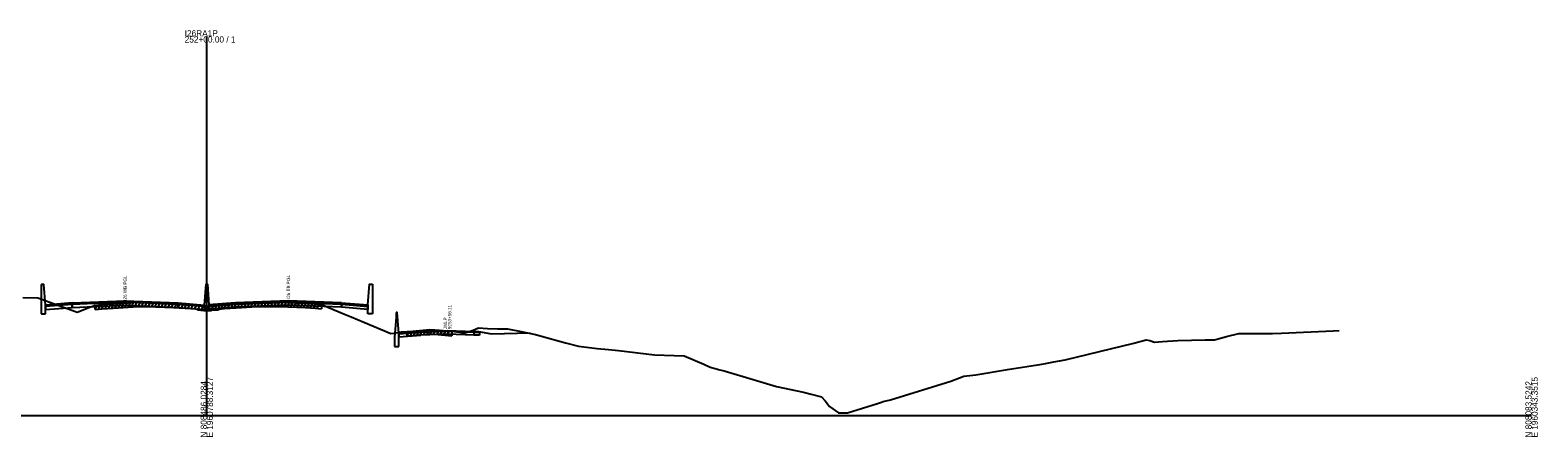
# Model space of a CAD drawing. Extents: x 1017 to 19997, y -1947 to 50737.
# Drawn here: x 10520 to 11203, y 1990 to 2175 of the extents above; entities that cross this region are included whole.
import ezdxf

# ---------------------------------------------------------------- set-up
doc = ezdxf.new("R2010")
doc.units = 0
for name, color, linetype in [('RD_GPK_XS_Cell', 7, 'Continuous'), ('RD_XS_Base', 7, 'Continuous'), ('RD_XS_ExGround', 7, 'Continuous'), ('RD_XS_ExPaveRet', 7, 'Continuous'), ('RD_XS_Greenside', 7, 'Continuous'), ('RD_XS_MedBWall', 7, 'Continuous'), ('RD_XS_Pave', 7, 'Continuous'), ('RD_XS_PaveOvlay', 7, 'Continuous'), ('RD_XS_TX_Notes', 7, 'Continuous')]:
    doc.layers.add(name, color=color, linetype=linetype)

msp = doc.modelspace()

# ---------------------------------------------------------------- linework, layer by layer
at = {"layer": 'RD_GPK_XS_Cell'}
for p, q in [((10600, 2000), (10600, 2171.99)), ((10000, 2000), (10600, 2000)), ((10600, 2000), (11200, 2000))]:
    msp.add_line(p, q, dxfattribs=at)
at = {"layer": 'RD_XS_Base'}
for points in [[(10539, 2050.38), (10527, 2049.42)], [(10527, 2049.42), (10527, 2048.08)], [(10527, 2048.08), (10539, 2049.04)], [(10539, 2049.04), (10539, 2050.38)], [(10539.05, 2049.05), (10539, 2049.04)], [(10539.05, 2050.39), (10539.05, 2049.05)], [(10539.05, 2049.05), (10563, 2050.02), (10587, 2049.05)], [(10587, 2049.05), (10587, 2050.39)], [(10599, 2049.45), (10587, 2050.39)], [(10587, 2049.05), (10599, 2048.11)], [(10599, 2048.11), (10599, 2049.45)], [(10601, 2048.18), (10601, 2049.52)], [(10613, 2049.12), (10601, 2048.18)], [(10613, 2049.12), (10613, 2050.46)], [(10660.95, 2049.13), (10637, 2050.09), (10613, 2049.12)], [(10660.95, 2049.13), (10660.95, 2050.47)], [(10661, 2049.12), (10660.95, 2049.13)], [(10661, 2050.46), (10661, 2049.12)], [(10661, 2050.46), (10673, 2049.5)], [(10661, 2049.12), (10661, 2050.46)], [(10673, 2048.16), (10661, 2049.12)], [(10673, 2049.5), (10673, 2048.16)], [(10697, 2037.82), (10687, 2037.02)], [(10687, 2037.02), (10687, 2035.69)], [(10687, 2035.69), (10697, 2036.49)], [(10697, 2037.82), (10709, 2038.3), (10721, 2037.82)], [(10697, 2036.49), (10697, 2037.82)], [(10721, 2036.51), (10709, 2036.97), (10697, 2036.49)], [(10721, 2037.82), (10721, 2036.51)], [(10721, 2037.82), (10723, 2037.74), (10723.5, 2037.72)], [(10723.5, 2036.39), (10721, 2036.51)], [(10723.5, 2037.72), (10723.5, 2036.39)]]:
    msp.add_lwpolyline(points, dxfattribs=at)
at = {"layer": 'RD_XS_ExGround'}
msp.add_lwpolyline([(10516.61, 2053.55), (10523.41, 2053.42), (10540.55, 2047.19), (10541.28, 2046.94), (10541.68, 2047.07), (10545.82, 2048.63), (10547.45, 2049.26), (10549.47, 2050.1), (10552.47, 2050.33), (10557.64, 2050.72), (10564.45, 2051.19), (10569.1, 2051.49), (10572.85, 2051.39), (10580.96, 2051.12), (10584.86, 2050.93), (10592.74, 2050.55), (10594.7, 2050.36), (10595.61, 2050.26), (10595.76, 2049.93), (10598.72, 2049.61), (10599.07, 2049.58), (10600, 2049.62), (10601.83, 2049.7), (10602.13, 2049.72), (10604.94, 2049.92), (10605.64, 2050.13), (10605.83, 2050.3), (10606.6, 2050.38), (10607.99, 2050.54), (10613.27, 2050.85), (10620.36, 2051.3), (10631.64, 2051.46), (10632.24, 2051.47), (10632.79, 2051.45), (10644.63, 2050.96), (10649.24, 2050.63), (10652, 2050.41), (10662.41, 2046.01), (10665.43, 2044.73), (10671.15, 2042.35), (10683.42, 2037.19), (10684.87, 2037.38), (10688.25, 2037.99), (10690.77, 2038.18), (10693.31, 2038.34), (10700.95, 2039.03), (10703.23, 2038.91), (10711.02, 2038.21), (10715.49, 2037.62), (10716.62, 2037.38), (10720.58, 2038.72), (10723.11, 2039.72), (10727.11, 2039.47), (10731.64, 2039.34), (10736.21, 2039.25), (10742.45, 2038.15), (10748.9, 2036.82), (10762.39, 2033.01), (10768.42, 2031.5), (10776.86, 2030.43), (10781.9, 2029.95), (10786.5, 2029.45), (10802.77, 2027.57), (10811.69, 2027.18), (10816.13, 2027.09), (10825.04, 2023.3), (10828.05, 2021.99), (10830.21, 2021.38), (10832.29, 2020.79), (10834.27, 2020.33), (10847.49, 2016.27), (10857.95, 2013.11), (10870.25, 2010.57), (10873.72, 2009.67), (10878.46, 2008.45), (10880.02, 2006.69), (10882, 2004.14), (10886.12, 2001.16), (10888.78, 2001.19), (10890.21, 2001.22), (10903.84, 2005.47), (10905.64, 2006.08), (10906.37, 2006.35), (10909.59, 2007.13), (10936.93, 2015.61), (10942.91, 2017.89), (10948.32, 2018.45), (10962.68, 2020.95), (10978.23, 2023.27), (10979.88, 2023.65), (10983.68, 2024.34), (10988.77, 2025.2), (11019.89, 2032.79), (11025.45, 2034.28), (11027.12, 2034), (11029.16, 2033.34), (11032.88, 2033.63), (11039.73, 2034), (11052.15, 2034.29), (11055.34, 2034.39), (11056.35, 2034.39), (11061.8, 2035.82), (11067.43, 2037.25), (11069.41, 2037.26), (11082.64, 2037.14), (11086.72, 2037.33), (11110.14, 2038.38), (11112.83, 2038.58)], dxfattribs=at)
at = {"layer": 'RD_XS_ExPaveRet'}
for p, q in [((10549.47, 2048.1), (10550.51, 2050.18)), ((10549.47, 2048.1), (10549.47, 2050.1)), ((10550.97, 2048.21), (10552.01, 2050.29)), ((10552.47, 2048.33), (10553.51, 2050.41)), ((10552.47, 2048.33), (10557.64, 2048.72)), ((10553.97, 2048.44), (10555.01, 2050.52)), ((10555.47, 2048.56), (10556.51, 2050.64)), ((10556.97, 2048.67), (10558.01, 2050.75)), ((10557.64, 2048.72), (10564.45, 2049.19)), ((10558.47, 2048.78), (10559.5, 2050.85)), ((10559.97, 2048.88), (10561, 2050.95)), ((10561.47, 2048.98), (10562.5, 2051.06)), ((10562.97, 2049.09), (10564, 2051.16)), ((10564.45, 2049.19), (10569.1, 2049.49)), ((10564.47, 2049.19), (10565.5, 2051.26)), ((10565.97, 2049.29), (10567, 2051.35)), ((10567.47, 2049.39), (10568.5, 2051.45)), ((10568.97, 2049.48), (10569.96, 2051.47)), ((10569.1, 2049.49), (10572.85, 2049.39)), ((10570.47, 2049.45), (10571.45, 2051.43)), ((10571.97, 2049.41), (10572.95, 2051.38)), ((10572.85, 2049.39), (10580.96, 2049.12)), ((10573.47, 2049.37), (10574.45, 2051.33)), ((10574.97, 2049.32), (10575.95, 2051.28)), ((10576.47, 2049.27), (10577.45, 2051.23)), ((10577.97, 2049.22), (10578.95, 2051.18)), ((10579.47, 2049.17), (10580.45, 2051.13)), ((10580.96, 2049.12), (10584.86, 2048.93)), ((10580.97, 2049.12), (10581.94, 2051.07)), ((10582.47, 2049.05), (10583.44, 2051)), ((10583.97, 2048.97), (10584.94, 2050.93)), ((10584.86, 2048.93), (10592.74, 2048.55)), ((10585.47, 2048.9), (10586.44, 2050.85)), ((10586.97, 2048.83), (10587.94, 2050.78)), ((10588.47, 2048.76), (10589.44, 2050.71)), ((10589.97, 2048.69), (10590.94, 2050.64)), ((10591.47, 2048.61), (10592.44, 2050.57)), ((10592.74, 2048.55), (10594.7, 2048.36)), ((10592.97, 2048.53), (10593.92, 2050.44)), ((10594.47, 2048.38), (10595.42, 2050.28)), ((10595.97, 2047.9), (10596.92, 2049.8)), ((10597.47, 2047.74), (10598.42, 2049.64)), ((10598.97, 2047.59), (10599.98, 2049.62)), ((10600.47, 2047.64), (10601.49, 2049.68)), ((10601.97, 2047.71), (10603, 2049.78)), ((10603.47, 2047.81), (10604.5, 2049.89)), ((10604.97, 2047.92), (10606.17, 2050.33)), ((10606.47, 2048.37), (10607.53, 2050.48)), ((10606.6, 2048.38), (10607.99, 2048.54)), ((10607.97, 2048.53), (10609, 2050.6)), ((10607.99, 2048.54), (10613.27, 2048.85)), ((10609.47, 2048.63), (10610.5, 2050.69)), ((10610.97, 2048.72), (10612, 2050.78)), ((10612.47, 2048.81), (10613.5, 2050.87)), ((10613.27, 2048.85), (10620.36, 2049.3)), ((10613.97, 2048.9), (10615, 2050.96)), ((10615.47, 2048.99), (10616.5, 2051.06)), ((10616.97, 2049.09), (10618, 2051.15)), ((10618.47, 2049.18), (10619.5, 2051.25)), ((10619.97, 2049.28), (10620.98, 2051.31)), ((10620.36, 2049.3), (10631.64, 2049.46)), ((10621.47, 2049.32), (10622.47, 2051.33)), ((10622.97, 2049.34), (10623.97, 2051.35)), ((10624.47, 2049.36), (10625.47, 2051.37)), ((10625.97, 2049.38), (10626.97, 2051.4)), ((10627.47, 2049.4), (10628.47, 2051.42)), ((10628.97, 2049.42), (10629.97, 2051.44)), ((10630.47, 2049.45), (10631.47, 2051.46)), ((10631.64, 2049.46), (10632.24, 2049.47)), ((10631.97, 2049.47), (10632.95, 2051.44)), ((10632.24, 2049.47), (10632.79, 2049.45)), ((10632.79, 2049.45), (10644.63, 2048.96)), ((10633.47, 2049.42), (10634.45, 2051.38)), ((10634.97, 2049.36), (10635.95, 2051.32)), ((10636.47, 2049.3), (10637.45, 2051.26)), ((10637.97, 2049.24), (10638.95, 2051.2)), ((10639.47, 2049.17), (10640.45, 2051.13)), ((10640.97, 2049.11), (10641.95, 2051.07)), ((10642.47, 2049.05), (10643.45, 2051.01)), ((10643.97, 2048.99), (10644.94, 2050.94)), ((10644.63, 2048.96), (10649.24, 2048.63)), ((10645.47, 2048.9), (10646.43, 2050.83)), ((10646.97, 2048.79), (10647.93, 2050.72)), ((10648.47, 2048.69), (10649.43, 2050.61)), ((10649.24, 2048.63), (10652, 2048.41)), ((10649.97, 2048.57), (10650.93, 2050.5)), ((10652, 2050.41), (10652, 2048.41)), ((10549.47, 2048.1), (10552.47, 2048.33)), ((10594.7, 2048.36), (10595.61, 2048.26)), ((10595.61, 2048.26), (10595.76, 2047.93)), ((10595.76, 2047.93), (10598.72, 2047.61)), ((10598.72, 2047.61), (10599.07, 2047.58)), ((10599.07, 2047.58), (10600, 2047.62)), ((10600, 2047.62), (10601.83, 2047.7)), ((10601.83, 2047.7), (10602.13, 2047.72)), ((10602.13, 2047.72), (10604.94, 2047.92)), ((10604.94, 2047.92), (10605.64, 2048.13)), ((10605.64, 2048.13), (10605.83, 2048.3)), ((10605.83, 2048.3), (10606.6, 2048.38)), ((10690.77, 2036.18), (10691.81, 2038.24)), ((10690.77, 2036.18), (10690.77, 2038.18)), ((10690.77, 2036.18), (10693.31, 2036.34)), ((10692.27, 2036.27), (10693.31, 2038.34)), ((10693.31, 2036.34), (10700.95, 2037.03)), ((10693.77, 2036.38), (10694.82, 2038.47)), ((10695.27, 2036.51), (10696.32, 2038.61)), ((10696.77, 2036.65), (10697.82, 2038.74)), ((10698.27, 2036.79), (10699.32, 2038.88)), ((10699.77, 2036.92), (10700.82, 2039.02)), ((10700.95, 2037.03), (10703.23, 2036.91)), ((10701.27, 2037.01), (10702.25, 2038.96)), ((10702.77, 2036.93), (10703.74, 2038.86)), ((10703.23, 2036.91), (10711.02, 2036.21)), ((10704.27, 2036.81), (10705.23, 2038.73)), ((10705.77, 2036.68), (10706.73, 2038.59)), ((10707.27, 2036.55), (10708.23, 2038.46)), ((10708.77, 2036.41), (10709.73, 2038.33)), ((10711.02, 2038.21), (10711.02, 2036.21))]:
    msp.add_line(p, q, dxfattribs=at)
at = {"layer": 'RD_XS_Greenside'}
for points in [[(10723, 2038.06), (10729, 2037.1)], [(10729, 2037.1), (10746.46, 2037.48)]]:
    msp.add_lwpolyline(points, dxfattribs=at)
at = {"layer": 'RD_XS_MedBWall'}
for points in [[(10527, 2050.1), (10526.25, 2059.44), (10525, 2059.44)], [(10525, 2059.44), (10525, 2046.1)], [(10599, 2050.11), (10599.75, 2059.52), (10600.25, 2059.52), (10601, 2050.18)], [(10673, 2050.18), (10673.75, 2059.52), (10675, 2059.52)], [(10675, 2059.52), (10675, 2046.18)], [(10527, 2046.1), (10527, 2050.1)], [(10599, 2048.11), (10599, 2050.11)], [(10601, 2050.18), (10601, 2048.11)], [(10673, 2046.18), (10673, 2050.18)], [(10525, 2046.1), (10527, 2046.1)], [(10601, 2048.11), (10599, 2048.11)], [(10675, 2046.18), (10673, 2046.18)], [(10685.75, 2044.68), (10685, 2035.34)], [(10687, 2037.34), (10686.25, 2046.68), (10685.75, 2046.68)], [(10685.75, 2046.68), (10685.75, 2044.68)], [(10685, 2035.34), (10685, 2031.34)], [(10687, 2031.34), (10687, 2037.34)], [(10685, 2031.34), (10687, 2031.34)]]:
    msp.add_lwpolyline(points, dxfattribs=at)
at = {"layer": 'RD_XS_Pave'}
for points in [[(10539, 2050.72), (10527, 2049.76)], [(10527, 2049.76), (10527, 2049.42)], [(10539, 2050.38), (10539, 2050.72)], [(10539.05, 2050.39), (10539, 2050.38)], [(10539.05, 2050.73), (10563, 2051.69), (10587, 2050.73)], [(10587, 2050.39), (10563, 2051.36), (10539.05, 2050.39)], [(10539.05, 2050.39), (10539.05, 2050.73)], [(10587, 2050.73), (10587, 2050.39)], [(10587, 2050.73), (10599, 2049.79)], [(10599, 2049.79), (10599, 2049.45)], [(10613, 2050.8), (10601, 2049.86)], [(10601, 2049.52), (10613, 2050.46)], [(10601, 2049.86), (10601, 2049.52)], [(10660.95, 2050.81), (10637, 2051.76), (10613, 2050.8)], [(10613, 2050.46), (10637, 2051.43), (10660.95, 2050.47)], [(10613, 2050.8), (10613, 2050.46)], [(10660.95, 2050.47), (10660.95, 2050.81)], [(10660.95, 2050.81), (10661, 2050.8)], [(10661, 2050.46), (10660.95, 2050.47)], [(10661, 2050.8), (10661, 2050.46)], [(10661, 2050.46), (10661, 2050.8)], [(10673, 2049.84), (10673, 2049.5)]]:
    msp.add_lwpolyline(points, dxfattribs=at)
at = {"layer": 'RD_XS_PaveOvlay'}
for points in [[(10539, 2051.06), (10527, 2050.1)], [(10527, 2050.1), (10527, 2049.76)], [(10539.05, 2051.07), (10539, 2051.06)], [(10539, 2051.06), (10539, 2050.72)], [(10539, 2050.72), (10539.05, 2050.73)], [(10539.05, 2051.07), (10563, 2052.03), (10587, 2051.07)], [(10539.05, 2050.73), (10539.05, 2051.07)], [(10587, 2051.07), (10587, 2050.73)], [(10587, 2051.07), (10599, 2050.11)], [(10599, 2050.11), (10599, 2049.79)], [(10613, 2051.14), (10601, 2050.18)], [(10601, 2050.18), (10601, 2049.86)], [(10660.95, 2051.14), (10637, 2052.1), (10613, 2051.14)], [(10613, 2051.14), (10613, 2050.8)], [(10660.95, 2050.81), (10660.95, 2051.14)], [(10660.95, 2051.14), (10661, 2051.14)], [(10661, 2051.14), (10661, 2050.8)], [(10661, 2051.14), (10673, 2050.18)], [(10661, 2050.8), (10661, 2051.14)], [(10673, 2049.84), (10661, 2050.8)], [(10673, 2050.18), (10673, 2049.84)], [(10697, 2038.14), (10687, 2037.34)], [(10687, 2037.02), (10697, 2037.82)], [(10687, 2037.34), (10687, 2037.02)], [(10697, 2038.14), (10709, 2038.62), (10721, 2038.14)], [(10721, 2037.82), (10709, 2038.3), (10697, 2037.82)], [(10697, 2037.82), (10697, 2038.14)], [(10721, 2038.14), (10721, 2037.82)], [(10721, 2038.14), (10723, 2038.06)], [(10723, 2037.74), (10721, 2037.82)], [(10723, 2038.06), (10723, 2037.74)]]:
    msp.add_lwpolyline(points, dxfattribs=at)

# ---------------------------------------------------------------- texts
at = {"layer": 'RD_GPK_XS_Cell'}
for s, p in [('252+00.00 / 1', (10590, 2169.19)), ('I26RA1P', (10590, 2171.99))]:
    msp.add_text(s, height=2.8, dxfattribs=at).set_placement(p)
for s, p in [('N 808486.0284', (10600, 1990)), ('E 1960788.3127', (10602.8, 1990)), ('N 808083.5242', (11200, 1990)), ('E 1960343.3515', (11202.8, 1990))]:
    msp.add_text(s, height=2.8, rotation=90, dxfattribs=at).set_placement(p)
at = {"layer": 'RD_XS_TX_Notes'}
for s, p in [('I26 WB PGL', (10563.75, 2052.03)), ('I26 EB PGL', (10637.75, 2052.83)), (' 9253+56.11', (10710.73, 2038.62)), (' JMLP', (10708.77, 2038.62))]:
    msp.add_text(s, height=1.5, rotation=90, dxfattribs=at).set_placement(p)

doc.saveas('drawing.dxf')
